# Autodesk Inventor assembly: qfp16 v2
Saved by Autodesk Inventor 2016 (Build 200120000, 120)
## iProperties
Created: 2016-09
Part Number: qfp16 v2
Document SubType Name: Assembly
Designer: Administrator
Author: Administrator
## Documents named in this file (3)
- c:\worker\convert-fusion-aug-2016\tmp\job-1\19\output\files\b1646d38-3d95-4128-a552-c87d2d1b62c9\qfp16 v2.iam
- c:\worker\convert-fusion-aug-2016\tmp\job-1\19\output\files\b1646d38-3d95-4128-a552-c87d2d1b62c9\Component21.ipt
- c:\worker\convert-fusion-aug-2016\tmp\job-1\19\output\files\b1646d38-3d95-4128-a552-c87d2d1b62c9\lead.ipt
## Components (2 placed, 2 different names)
1. Component21:1
2. lead:1
